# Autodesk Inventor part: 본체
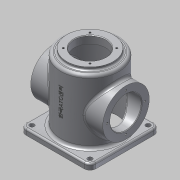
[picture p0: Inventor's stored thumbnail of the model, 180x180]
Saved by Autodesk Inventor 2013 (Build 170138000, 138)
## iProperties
Created: 2015-10
Part Number: 본체
Material: 알루미늄 6061
Document SubType Name: Modeling
Designer: Administrator
Density: 2.71 g/cm^3
Mass: 987.032 g
Surface Area: 1039.63 cm^2
Volume: 364.218 cm^3
Author: Administrator
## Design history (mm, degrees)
sketch "스케치1"
  geometry: L1 (-60, 60)-(60, 60); L2 (60, 60)-(60, -60); L3 (60, -60)-(-60, -60); L4 (-60, -60)-(-60, 60); 1 further point
  constraints: 8 end point, 2 parallel, 1 horizontal, 1 perpendicular
  dimensions: "d0" = 120 distance between parallel lines of L3 L1; "d2" = 120 distance between parallel lines of L2 L4; "d3" = 60 distance from line of point (0, 0) L1; "d4" = 60 distance from line of point (0, 0) L4
extrude "돌출1" new body sketch "스케치1" distance "d5" = 10; taper "d6" = 0 deg
sketch "스케치2"
  geometry: C1 r 50 at (0, 0); 1 further point
  constraints: 1 centre point, 1 coincident
  dimensions: "d7" = 100 diameter of C1
extrude "돌출2" join sketch "스케치2" distance "d9" = 110; taper "d10" = 0 deg
sketch "스케치3"
  geometry: C1 r 50 at (0, 0) reference; C2 r 40 at (0, 0)
  constraints: 1 centre point, 1 coincident
  dimensions: "d11" = 80 diameter of C2
extrude "돌출3" join sketch "스케치3" distance "d13" = 5; taper "d14" = 0 deg
sketch "스케치4"
  geometry: C1 r 50 at (0, 0) reference; C2 r 4 at (-50, 50); C3 r 4 at (50, 50); C4 r 4 at (50, -50); C5 r 4 at (-50, -50)
  constraints: 4 centre point
  dimensions: "d15" = 8 diameter of C2; "d17" = 8 diameter of C3; "d18" = 8 diameter of C4; "d19" = 8 diameter of C5; "d20" = 100 distance of C3.centre C2.centre; "d21" = 50 horizontal distance of C1.centre C2.centre; "d22" = 100 distance of C4.centre C3.centre; "d23" = 50 horizontal distance of C1.centre C3.centre; "d24" = 100 distance of C5.centre C4.centre; "d25" = 50 horizontal distance of C1.centre C4.centre; "d26" = 100 distance of C2.centre C5.centre; "d27" = 50 horizontal distance of C1.centre C2.centre
extrude "돌출4" cut sketch "스케치4" stored distance "d28" = 5; taper "d29" = 0 deg
node "작업 평면1"
sketch "스케치5"
  geometry: C1 r 40 at (0, 60); 1 further point
  constraints: 1 centre point
  dimensions: "d31" = 80 diameter of C1; "d33" = 60 distance of point (0, 0) C1.centre; "d34" = 0 horizontal distance of point (0, 0) C1.centre
extrude "돌출5" join sketch "스케치5" stored distance "d35" = 5; taper "d36" = 0 deg
node "작업 평면2"
sketch "스케치6"
  geometry: C1 r 40 at (0, 60); 1 further point
  constraints: 1 centre point
  dimensions: "d38" = 80 diameter of C1; "d40" = 60 distance of point (0, 0) C1.centre; "d41" = 0 horizontal distance of point (0, 0) C1.centre
extrude "돌출6" join sketch "스케치6" stored distance "d42" = 5; taper "d43" = 0 deg
sketch "스케치7"
  geometry: C1 r 45 at (0, 0); 1 further point
  constraints: 1 centre point, 1 coincident
  dimensions: "d44" = 90 diameter of C1
extrude "돌출7" cut sketch "스케치7" distance "d46" = 112; taper "d47" = 0 deg
sketch "스케치8"
  geometry: C1 r 40 at (0, 0) reference; C2 r 27 at (0, 0)
  constraints: 1 centre point, 1 coincident
  dimensions: "d48" = 54 diameter of C2
extrude "돌출8" cut sketch "스케치8" stored distance "d50" = 112; taper "d51" = 0 deg
sketch "스케치9"
  geometry: C1 r 40 at (0, 0) reference; C2 r 27 at (0, 0); 1 further point
  constraints: 1 centre point, 1 coincident
  dimensions: "d52" = 54 diameter of C2
extrude "돌출9" cut sketch "스케치9" stored distance "d54" = 112; taper "d55" = 0 deg
sketch "스케치10"
  geometry: C1 r 40 at (0, 0) reference; C2 r 27 at (0, 0); 1 further point
  constraints: 1 centre point, 1 coincident
  dimensions: "d56" = 54 diameter of C2
extrude "돌출10" cut sketch "스케치10" stored distance "d58" = 112; taper "d59" = 0 deg
sketch "스케치11" dims "d60" = 65
  geometry: L1 (0, 0)-(0, 32.5); C1 r 40 at (0, 0) reference; C2 r 2 at (0, 32.5); 1 further point
  constraints: 2 coincident, 2 end point, 1 centre point, 1 vertical, 1 vertical alignment, 2 other
  dimensions: "d62" = 4 diameter of C2
hole "구멍1" sketch "스케치11" at (0, 32.5) diameter "d63" = 3.242; stored, may be unused: countersink angle "d67" = 90 deg, drill point angle "d69" = 118 deg; dims "d64" = 8, "d65" = 4, "d66" = 2, "d68" = 10
sketch "스케치12" dims "d73" = 65
  geometry: L1 (0, 0)-(0, 32.5); C1 r 40 at (0, 0) reference; C2 r 2 at (0, 32.5); 1 further point
  constraints: 2 coincident, 2 end point, 1 centre point, 1 vertical, 1 vertical alignment, 2 other
  dimensions: "d75" = 4 diameter of C2
hole "구멍2" sketch "스케치12" at (0, 32.5) diameter "d76" = 3.242; stored, may be unused: countersink angle "d80" = 90 deg, drill point angle "d82" = 118 deg; dims "d77" = 8, "d78" = 4, "d79" = 2, "d81" = 10
sketch "스케치13"
  geometry: L1 (0, 0)-(0, 32.5); L2 (0, 0)-(22.981, 22.981); C1 r 40 at (0, 0) reference; C2 r 2 at (22.981, 22.981); A1 r 32.5 centre (0, 0) between (0, 32.5) and (22.981, 22.981)
  constraints: 4 end point, 2 centre point, 2 coincident, 2 point on circle, 1 vertical
  dimensions: "d86" = 65 diameter of A1; "d88" = 45 deg angle of L2 L1; "d90" = 4 diameter of C2
hole "구멍3" sketch "스케치13" at (22.981, 22.981) diameter "d91" = 3.242; stored, may be unused: countersink angle "d95" = 90 deg, drill point angle "d97" = 118 deg; dims "d92" = 8, "d93" = 4, "d94" = 2, "d96" = 10
node "작업 평면3"
sketch "스케치14"
  geometry: L1 (-3.602, 45.113)-(-3.602, 94.887); L2 (-3.602, 94.887)-(3.602, 94.887); L3 (3.602, 94.887)-(3.602, 45.113); L4 (3.602, 45.113)-(-3.602, 45.113); L5 (0, 45.113)-(0, 94.887); L6 (-3.602, 70)-(3.602, 70); 1 further point
  constraints: 4 end point, 4 midpoint, 2 other
  dimensions: "d104" = 0 distance from line of point (0, 0) L5; "d105" = 70 distance from line of point (0, 0) L6
feature "엠보싱1" sketch "스케치14" dims "d0" = 120, "d2" = 120, "d3" = 60, "d4" = 60, "d106" = 0.5, "d107" = 0
fillet "모깎기1" dims "d108" = 10
fillet "모깎기2" dims "d109" = 5
fillet "모깎기3" dims "d110" = 5
chamfer "모따기1" distance "d111" = 3; stored, may be unused: second distance "d112" = 2, angle "d113" = 45 deg
chamfer "모따기2" distance "d114" = 1; stored, may be unused: second distance "d115" = 2, angle "d116" = 45 deg
fillet "모깎기4" dims "d117" = 3
fillet "모깎기5" dims "d118" = 5
fillet "모깎기6" dims "d119" = 3
fillet "모깎기7" dims "d120" = 3
node "솔리드1"
pattern_circular "원형 패턴1" dims angle "d71" = 360 deg
pattern_circular "원형 패턴2" dims angle "d84" = 360 deg
pattern_circular "원형 패턴3" dims angle "d99" = 360 deg
other parameters: "d30" = 62, "d37" = -62, "d101" = -53.75
